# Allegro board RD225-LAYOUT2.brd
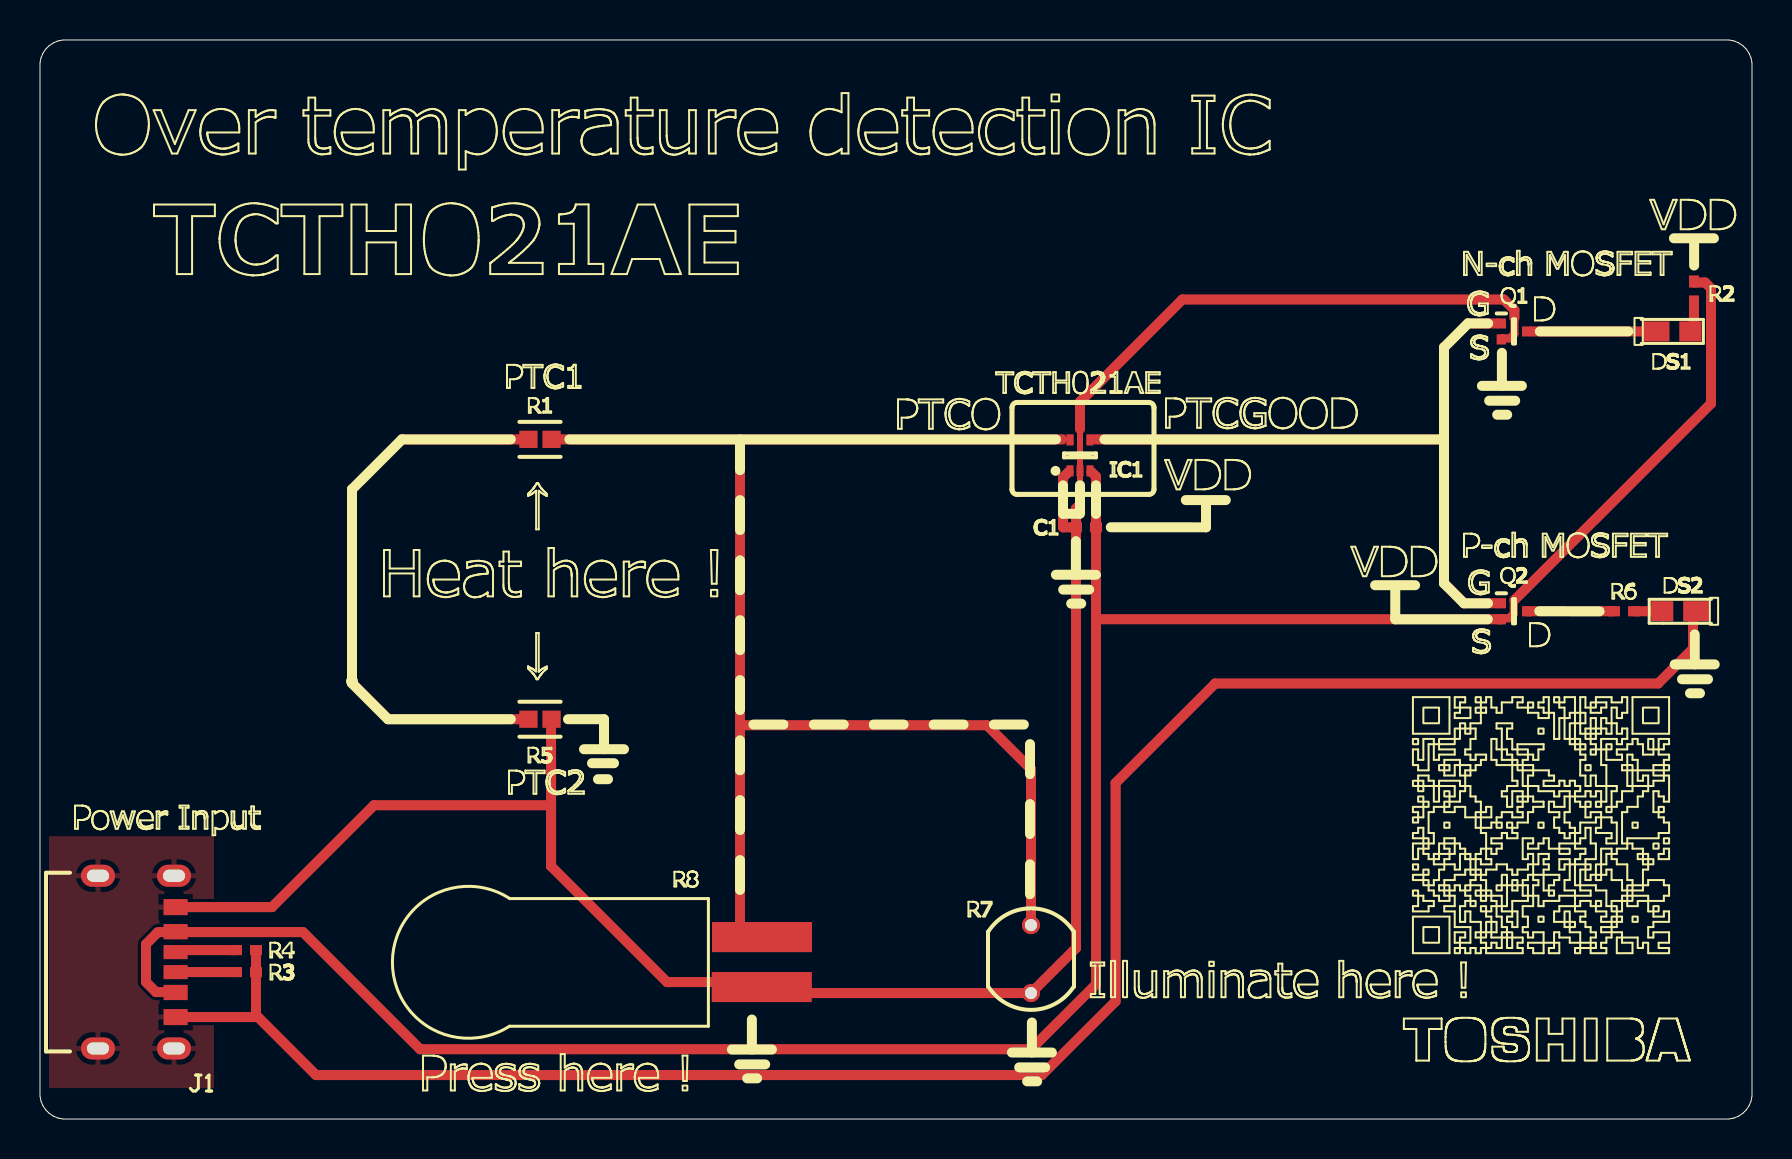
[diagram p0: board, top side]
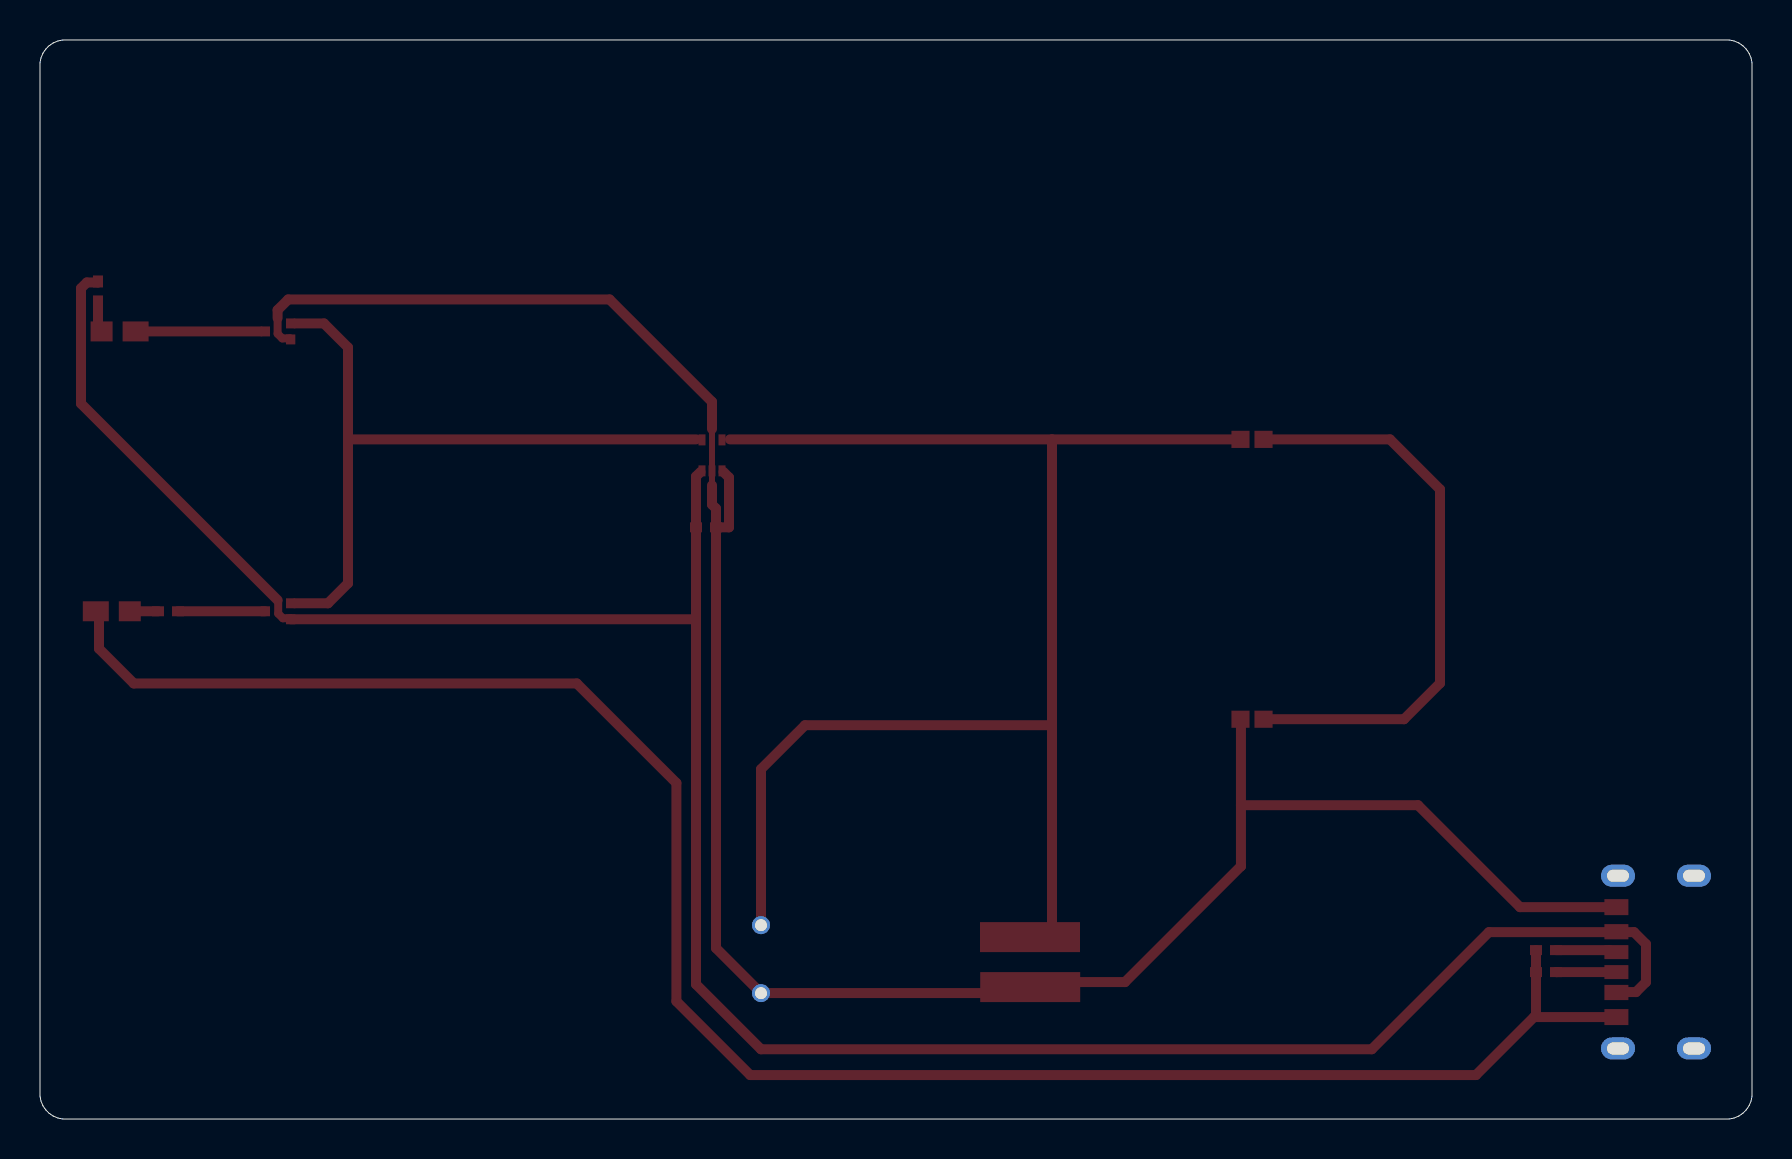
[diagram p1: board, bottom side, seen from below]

Outline 85.6 x 53.98 mm; copper layers: TOP, BOTTOM. Coordinates in mm from the lower left corner of the outline.
Outline path: 0,52.84 0.05,53.08 0.14,53.31 0.28,53.52 0.46,53.7 0.67,53.84 0.9,53.93 1.14,53.98 84.46,53.98 84.7,53.93 84.93,53.84 85.14,53.7 85.32,53.52 85.46,53.31 85.55,53.08 85.6,52.84 85.6,1.14 85.55,0.9 85.46,0.67 85.32,0.46 85.14,0.28 84.93,0.14 84.7,0.05 84.46,0 1.14,0 0.9,0.05 0.67,0.14 0.46,0.28 0.28,0.46 0.14,0.67 0.05,0.9 0,1.14 0,52.84

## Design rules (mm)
constraint set DEFAULT: 

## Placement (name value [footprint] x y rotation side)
C1  -  [1005_0402_HIGH_DENSI_1]  52.3 29.6 0 top
DS1  -  [1608_0603_LED__TOSHI_1]  81.67 39.4 180 top
DS2  -  [1608_0603_LED__TOSHI_1]  81.96 25.4 0 top
IC1  -  [TCTH0XXXE]  52 33.2 90 top
J1  -  [USB4125GFA0190]  3.7 7.85 270 top
Q1  -  [SOTFL40P120X55_3N]  73.7 39.4 0 top
Q2  -  [SOTFL40P120X55_3N]  73.7 25.4 0 top
R1  -  [FP_PRF18_PRG18_0_15__1]  25 34 0 top
R2  -  [1005_0402_HIGH_DENSI_1]  82.7 41.4 90 top
R3  -  [1005_0402_HIGH_DENSI_1]  10.3 7.35 180 top
R4  -  [1005_0402_HIGH_DENSI_1]  10.3 8.45 180 top
R5  -  [FP_PRF18_PRG18_0_15__1]  25 20 180 top
R6  -  [1005_0402_HIGH_DENSI_1]  79.2 25.4 180 top
R7  -  [PDV_P8104]  49.55 9.7 180 top
R8  -  [FSR_MODEL400_SHORT]  25.22 7.85 90 top

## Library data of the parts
C1 = C
DS1 DS2 = LED
IC1 = TCTH021AE: alternate symbols: (T:TCTH0xxxE;B:TCTH0xxxE_B)
J1 = USB4125-GF-A-0190: alternate symbols: (T:USB4125GFA0190;B:USB4125GFA0190_B)
Q1 = SSM3K35MFV
Q2 = SSM3J35AMFV: alternate symbols: (T:SOTFL40P120X55_3N;B:SOTFL40P120X55_3N_B)
R1 = PRF18BG471RB5RB: alternate symbols: (T:FP_PRF18_PRG18_0_15__1;B:FP_PRF18_PRG18_0_15__1_B)
R2-R4 R6 = R
R5 = PRF18BD471RB5RB: alternate symbols: (R5_FP_PRF18_PRG18_0__1)
R7 = CDS: alternate symbols: (T:PDV_P8104;B:PDV_P8104_B)
R8 = FSR400_SHORT: alternate symbols: (T:FSR_Model400_Short;B:FSR_Model400_Short_B)

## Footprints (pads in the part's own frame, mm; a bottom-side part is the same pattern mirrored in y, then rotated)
1005_0402_HIGH_DENSI_1
  rect 0.6x0.5 smd: 1(-0.5,0) 2(0.5,0)
1608_0603_LED__TOSHI_1
  rect 1.1x1 smd: 1(-0.85,0)
  rect 1.3x1 smd: 2(0.85,0)
FP_PRF18_PRG18_0_15__1
  rect 0.906x0.858 smd: 1(-0.576,0) 2(0.576,0)
FSR_MODEL400_SHORT
  rect 1.5x5 smd: 1(-1.25,-10.87) 2(1.25,-10.88)
PDV_P8104
  round 0.9 hole 0.6: 1(0,0) 2(0,3.4)
SOTFL40P120X55_3N
  rect 0.465x0.5 smd: 1(-0.632,0.4) 2(-0.632,-0.4) 3(0.632,0)
TCTH0XXXE
  rect 0.55x0.35 smd: 1(-0.775,0.5) 2(-0.775,0) 3(-0.775,-0.5) 4(0.775,-0.5) 5(0.775,0.5)
USB4125GFA0190
  rect 0.7x1.2 smd: A5(-0.5,3.08) B5(0.5,3.08)
  rect 0.76x1.2 smd: A9(1.52,3.08) B9(-1.52,3.08)
  rect 0.8x1.2 smd: A12(2.75,3.08) B12(-2.75,3.08)
  oval 1.1x1.7 hole 0.6x1.1: MH1(-4.32,3) MH2(-4.32,-0.8) MH3(4.32,-0.8) MH4(4.32,3)

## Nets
GND: C1.1 DS2.2 IC1.1 IC1.2 J1.A12 J1.B12 J1.MH1 J1.MH2 J1.MH3 J1.MH4 Q1.2 R3.1 R4.1 R5.1 R7.2 R8.1
NETDS1_1: DS1.1 R2.1
NETDS1_2: DS1.2 Q1.3
NETDS2_1: DS2.1 R6.1
NETJ1_A5: J1.A5 R4.2
NETJ1_B5: J1.B5 R3.2
NETQ2_3: Q2.3 R6.2
NETR1_1: R1.1 R5.2
PTCGOOD: IC1.4 Q1.1 Q2.1
PTCO: IC1.5 R1.2 R7.1 R8.2
VP_5R0_MCU: C1.2 IC1.3 J1.A9 J1.B9 Q2.2 R2.2

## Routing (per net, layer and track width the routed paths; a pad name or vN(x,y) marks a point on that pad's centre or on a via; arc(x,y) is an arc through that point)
GND: length 212.7
  TOP w0.3: 52,31.7 52,34.52 ; 10.8,5.2 10.9,5.1
  TOP w0.4: 73.72,40.07 73.72,39.28 73.49,39.05 73.1,39.05 73.07,39.02 Q1.2
  TOP w0.5: 73.72,40.07 73.72,40.47 73.19,41 57.12,41 52,35.88 52,34.52 ; C1.1 51.8,30.54 52,30.74 52,31.7 ; C1.1 51.15,29.6 51.15,32.09 51.42,32.37 ; C1.1 51.8,8.55 R7.2 36.39,6.3 R8.1 ; 36.2,6.71 36.07,6.85 31.35,6.85 25.55,12.65 25.55,12.65 25.55,15.7 ; 82.65,25.4 82.65,23.53 80.91,21.79 58.76,21.79 53.78,16.81 53.78,5.89 50.09,2.2 13.8,2.2 10.9,5.1 J1.A12 ; 10.8,5.2 R3.1 R4.1 ; 25.55,15.7 16.7,15.7 11.6,10.6 J1.B12 ; 25.55,15.7 25.55,20
NETDS1_1: length 1.5
  TOP w0.5: 82.65,39.4 82.7,39.45 R2.1
NETDS1_2: length 6.2
  TOP w0.5: 74.58,39.4 DS1.2
NETDS2_1: length 1.4
  TOP w0.5: R6.1 DS2.1
NETJ1_A5: length 3.1
  TOP w0.5: R4.2 7.13,8.45 7.03,8.35 J1.A5
NETJ1_B5: length 3
  TOP w0.5: R3.2 J1.B5
NETQ2_3: length 4.3
  TOP w0.5: 74.36,25.4 R6.2
NETR1_1: length 29.2
  TOP w0.5: R5.2 17.4,20 15.6,21.8 15.6,31.5 18.1,34 24.31,34 24.37,34.05 R1.1
PTCGOOD: length 35.4
  TOP w0.5: 70.2,34 70.2,38.6 71.4,39.8 72.82,39.8 ; 70.2,34 52.8,34 ; 70.2,34 70.2,26.8 71.2,25.8 72.83,25.8
PTCO: length 74.9
  TOP w0.5: 35,34 35,9 35.1,9.1 R8.2 ; 35,34 R1.2 ; 35,34 51.1,34 ; R7.1 49.55,17.5 47.35,19.7 35.05,19.7
VP_5R0_MCU: length 123.2
  TOP w0.4: 73.72,25.96 73.69,25.93 73.69,25.28 73.46,25.05 73.1,25.05 73.07,25.02 Q2.2
  TOP w0.5: 52.8,25 52.8,6.74 49.55,3.49 19.01,3.49 13.15,9.35 5.9,9.35 5.3,8.75 5.3,6.85 5.8,6.35 6.76,6.35 J1.A9 ; 52.8,25 C1.2 52.8,32.14 52.58,32.37 ; 52.8,25 Q2.2 ; R2.2 82.7,41.85 83.26,41.85 83.55,41.56 83.55,35.79 73.72,25.96

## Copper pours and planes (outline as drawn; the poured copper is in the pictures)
GND on TOP: 8.7,1.55 0.45,1.55 0.45,14.15 8.7,14.15 8.7,11.01 7.63,11.01 7.63,11.25 7.17,11.25 7.17,11.38 7.21,11.39 7.41,11.47 7.57,11.6 7.7,11.76 7.78,11.96 7.79,12.04 5.61,12.04 5.62,11.96 5.7,11.76 5.83,11.6 5.99,11.47 6.19,11.39 6.23,11.38 6.23,11.25 5.93,11.25 5.93,10.73 6.78,10.73 6.78,10.47 5.93,10.47 5.93,9.95 6.03,9.9 6.03,9.76 5.9,9.76 5.74,9.73 5.61,9.64 5.01,9.04 4.92,8.91 4.89,8.75 4.89,6.85 4.92,6.69 5.01,6.56 5.51,6.06 5.64,5.97 5.8,5.94 6.03,5.94 6.03,5.8 5.93,5.75 5.93,5.23 6.78,5.23 6.78,4.97 5.93,4.97 5.93,4.45 6.23,4.45 6.23,4.32 6.19,4.31 5.99,4.23 5.83,4.1 5.7,3.94 5.62,3.74 5.61,3.66 7.79,3.66 7.78,3.74 7.7,3.94 7.57,4.1 7.41,4.23 7.21,4.31 7.17,4.32 7.17,4.45 7.63,4.45 7.63,4.69 8.7,4.69 ; 12 cut-outs

Small or netless copper shapes (teardrops, artwork), in the pictures only: 4 on TOP
